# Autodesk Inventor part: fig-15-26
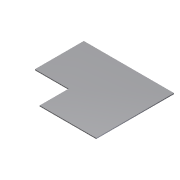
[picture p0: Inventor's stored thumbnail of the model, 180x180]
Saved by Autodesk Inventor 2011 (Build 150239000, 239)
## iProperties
Created: 2005-03
Part Number: fig-15-26
Document SubType Name: Sheet Metal
Designer: CADCIM
Manufacturer: Standard
Standards Organization: Custom
Density: 1 g/cm^3
Sheet Metal Rule: Default
Author: CADCIM
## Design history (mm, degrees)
node "Face1"
  sketch "Sketch1"
    geometry: L1 (29.25, 32.25)-(-19.875, 32.25); L2 (-19.875, 32.25)-(-19.875, 5.625); L3 (-19.875, 5.625)-(-1.5, 5.625); L4 (-1.5, 5.625)-(-1.5, -10.125); L5 (-1.5, -10.125)-(29.25, -10.125); L6 (29.25, -10.125)-(29.25, 32.25)
    constraints: 12 end point, 4 parallel, 1 horizontal, 1 perpendicular
body "Solid1"
face "Plate1" dims "Thickness" = 0.5
other parameters: "BendRadius" = 0.5 (= Thickness), "BendReliefWidth" = 0.5 (= Thickness), "BendReliefDepth" = 0.25 (= 0.5 x Thickness), "CornerReliefSize" = 2 (= 4 x Thickness), "SeamGap" = 0.01, "MinimumRemnant" = 1 (= 2 x Thickness), "TransitionRadius" = 0.5 (= BendRadius), "JacobiRadiusSize" = 0.5 (= Thickness), "GapSize" = 0.5 (= Thickness), "d0" = 0.5 (= BendRadius)
